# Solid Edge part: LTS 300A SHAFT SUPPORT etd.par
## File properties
Author: davee
Template: Normal.par
Last saved by: davee
Revision: 10
Application: Solid Edge
Accuracy: 0.990
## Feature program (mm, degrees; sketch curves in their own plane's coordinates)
sketch for "unnamed Protrusion 1" #1 plane through (0, 0, 0) normal (0, 0, 1) x-axis (1, 0, 0)
  line (9.5, -14.5) -> (28.5, -14.5)
  line (28.5, -14.5) -> (28.5, 10)
  line (28.5, 10) -> (9.5, 10)
  line (9.5, 10) -> (9.5, -14.5)
sketch for "unnamed Protrusion 1" #2 plane through (0, 0, 0) normal (0, 0, 1) x-axis (1, 0, 0)
  line (-28.5, -10) -> (-9.5, -10)
  line (-9.5, -10) -> (-9.5, 10)
  line (-9.5, 10) -> (-28.5, 10)
  line (-28.5, 10) -> (-28.5, -10)
  dimension (linear) = 9.5
  dimension (linear) = 28.5
  dimension (linear) = 28.5
  dimension (linear) = 28.5
extrude "unnamed Protrusion 1" add finite 13 along +normal
sketch for "ExtrudedProtrusion_2" plane through (-18.5, 0, 13) normal (0, 0, 1) x-axis (1, 0, 0)
  line (-10, 10) -> (47, 10)
  line (47, 2) -> (47, 10)
  line (-10, 2) -> (47, 2)
  line (-10, 10) -> (-10, 2)
extrude "ExtrudedProtrusion_2" add finite 57.5 along +normal
sketch for "unnamed Cutout 1" plane through (0, 2, 41.75) normal (0, -1, 0) x-axis (1, 0, 0)
  circle centre (0, 2.25) radius 10
extrude "unnamed Cutout 1" cut through along -normal
sketch for "ExtrudedCutout_2" plane through (0, 2, 41.75) normal (0, -1, 0) x-axis (1, 0, 0)
  line (2.45, 13.25) -> (6.3509, 13.25)
  line (6.3509, 13.25) -> (12.7017, 2.25)
  line (12.7017, 2.25) -> (6.3509, -8.75)
  line (2.45, -8.75) -> (6.3509, -8.75)
  line (2.45, -7.75) -> (2.45, -8.75)
  line (-2.45, -7.75) -> (2.45, -7.75)
  line (-2.45, -7.75) -> (-2.45, -8.75)
  line (-6.3509, -8.75) -> (-2.45, -8.75)
  line (-12.7017, 2.25) -> (-6.3509, -8.75)
  line (-6.3509, 13.25) -> (-12.7017, 2.25)
  line (-6.3509, 13.25) -> (-2.45, 13.25)
  line (-2.45, 13.25) -> (-2.45, 12.25)
  line (-2.45, 12.25) -> (2.45, 12.25)
  line (2.45, 12.25) -> (2.45, 13.25)
  dimension (linear) = 6.3509
  dimension (linear) = 6.3509
  dimension (linear) = 6.3509
  dimension (linear) = 12.7017
  dimension (linear) = 6.3509
  dimension (linear) = 12.7017
  dimension (linear) = 2.45
  dimension (linear) = 2.45
extrude "ExtrudedCutout_2" cut finite 4 along -normal
sketch for "Hole_1" plane through (-18.5, 0, 0) normal (0, 0, -1) x-axis (1, 0, 0)
  hole centre (35.5, 6.5) bore radius 1.1
hole "Hole_1" diameter 2.2 through
sketch for "unnamed Hole 1" plane through (-18.5, 0, 0) normal (0, 0, -1) x-axis (1, 0, 0)
  hole centre (1.5, 2) bore radius 1.1
hole "unnamed Hole 1" through
sketch for "Hole_3" plane through (-18.5, 0, 0) normal (0, 0, -1) x-axis (1, 0, 0)
  hole centre (1.5, 2) bore radius 2.2
hole "Hole_3" diameter 4.4 finite  VBottomAngle = 118 deg
sketch for "unnamed Hole 2" plane through (-18.5, 0, 0) normal (0, 0, -1) x-axis (1, 0, 0)
  hole centre (35.5, 6.5) bore radius 2.2
hole "unnamed Hole 2" finite
sketch for "Hole_5" plane through (-19, 0, 0) normal (0, 0, -1) x-axis (1, 0, 0)
  hole centre (-2, 2) bore radius 1.65
hole "Hole_5" diameter 3.3 through
sketch for "unnamed Hole 3" plane through (-19, 0, 0) normal (0, 0, -1) x-axis (1, 0, 0)
  hole centre (40, 6.5) bore radius 1.65
hole "unnamed Hole 3" through
sketch for "ExtrudedCutout_3" #1 plane through (-19, -4, 0) normal (0, 0, -1) x-axis (1, 0, 0)
  line (36, 1.5) -> (40, 1.5)
  line (40, 1.5) -> (40, 3.5)
  line (40, 3.5) -> (36, 3.5)
  line (36, 3.5) -> (36, 1.5)
sketch for "ExtrudedCutout_3" #2 plane through (-19, -4, 0) normal (0, 0, -1) x-axis (1, 0, 0)
  line (-2, -3) -> (2, -3)
  line (2, -3) -> (2, -1)
  line (2, -1) -> (-2, -1)
  line (-2, -1) -> (-2, -3)
extrude "ExtrudedCutout_3" cut finite 8 along -normal
sketch for "ExtrudedProtrusion_4" plane through (-19, -4, 13) normal (0, 0, 1) x-axis (1, 0, 0)
  line (5.9213, -0.4) -> (32.0787, -0.4)
  line (32.0787, -0.4) -> (32.0787, 14)
  line (5.9213, 14) -> (32.0787, 14)
  line (5.9213, 14) -> (5.9213, -0.4)
extrude "ExtrudedProtrusion_4" add finite 5.5 along -normal
sketch for "ExtrudedCutout_4" plane through (0, 2, 41.75) normal (0, -1, 0) x-axis (1, 0, 0)
  circle centre (0, -4.25) radius 27
extrude "ExtrudedCutout_4" cut finite 69.85 along +normal
sketch for "ExtrudedCutout_8" plane through (0, 2, 40.5) normal (0, -1, 0) x-axis (1, 0, 0)
  line (25.5, -27.5) -> (28.5, -27.5)
  line (25.5, 3.5) -> (25.5, -27.5)
  line (-25.5, 3.5) -> (-25.5, -27.5)
  line (-28.5, -27.5) -> (-25.5, -27.5)
  line (-28.5, 30) -> (-28.5, -27.5)
  line (-28.5, 30) -> (28.5, 30)
  line (28.5, 30) -> (28.5, -27.4)
extrude "ExtrudedCutout_8" cut finite 4 along -normal
sketch for "ExtrudedProtrusion_5" plane through (0, 6, 41.75) normal (0, -1, 0) x-axis (1, 0, 0)
  line (-25.5, 28.75) -> (-25.5, -28.75)
  line (-25.5, -28.75) -> (-28.5, -28.75)
  line (-28.5, 28.75) -> (-28.5, -28.75)
  line (-28.5, 28.75) -> (-25.5, 28.75)
extrude "ExtrudedProtrusion_5" add finite 20 along +normal
sketch for "ExtrudedCutout_9" plane through (-28.5, -2, 35.25) normal (-1, 0, 0) x-axis (0, -1, 0)
  line (-8, 35.25) -> (6, -15.45)
  line (6, -22.25) -> (6, -15.45)
  line (6, -22.25) -> (18.4691, -22.25)
  dimension (linear) = 6
  dimension (linear) = 6
extrude "ExtrudedCutout_9" cut finite 3 along -normal
sketch for "ExtrudedProtrusion_6" plane through (1.5, 6, 41.75) normal (0, -1, 0) x-axis (1, 0, 0)
  line (24, -28.75) -> (24, 28.75)
  line (24, 28.75) -> (27, 28.75)
  line (27, 28.75) -> (27, -28.75)
  line (27, -28.75) -> (24, -28.75)
extrude "ExtrudedProtrusion_6" add finite 31.75 along +normal
sketch for "ExtrudedCutout_10" plane through (28.5, -7.875, 35.25) normal (1, 0, 0) x-axis (0, 1, 0)
  line (-6.625, -22.25) -> (-4.625, -22.25)
  line (-4.625, -16.07) -> (-4.625, -22.25)
  line (13.875, 35.25) -> (-4.625, -16.07)
  dimension (linear) = 6.625
  dimension (linear) = 4.625
extrude "ExtrudedCutout_10" cut finite 3 along -normal
fillet "Round_1" radius 2
fillet "Round_2" radius 3
fillet "Round_3" radius 0.8
pattern "unnamed Pattern 1" of "Hole_1", "unnamed Hole 1"
pattern "unnamed Pattern 2" of "Hole_3", "unnamed Hole 2"
pattern "unnamed Pattern 3" of "Hole_5", "unnamed Hole 3"
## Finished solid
Body 1: solid body, 89 faces, 205 edges, 116 vertices.
  Faces by surface: plane 43, cylinder 32, sphere 6, torus 4, blend 2, cone 2
  Edges by curve: line 136, circle 59, ellipse 10
Bounding box of the edges (mm; curved faces can reach further): 57.000 x 24.500 x 70.500, from (-28.5, -14.5, 0) to (28.5, 10, 70.5).
Cylindrical faces by radius (mm): R0.8 x3, R1.1 x2, R1.65 x2, R2 x19, R2.2 x2, R3 x2, R10 x1, R25.5 x1
Conical faces (half-angle, radius in mm at the cone's reference point): 59 deg R2.2 x2
Toroidal faces (ring radius, tube radius in mm): R2.2 r0.8 x2, R4 r2 x2
Spherical faces by radius (mm): R2 x6
Planar faces by outward normal: +x 5, +y 3, +z 5, -x 5, -y 11, -z 8, oblique 6
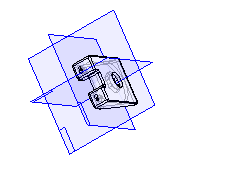
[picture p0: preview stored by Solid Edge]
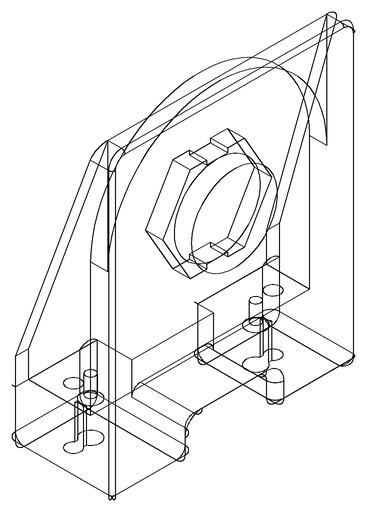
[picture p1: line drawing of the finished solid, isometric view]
